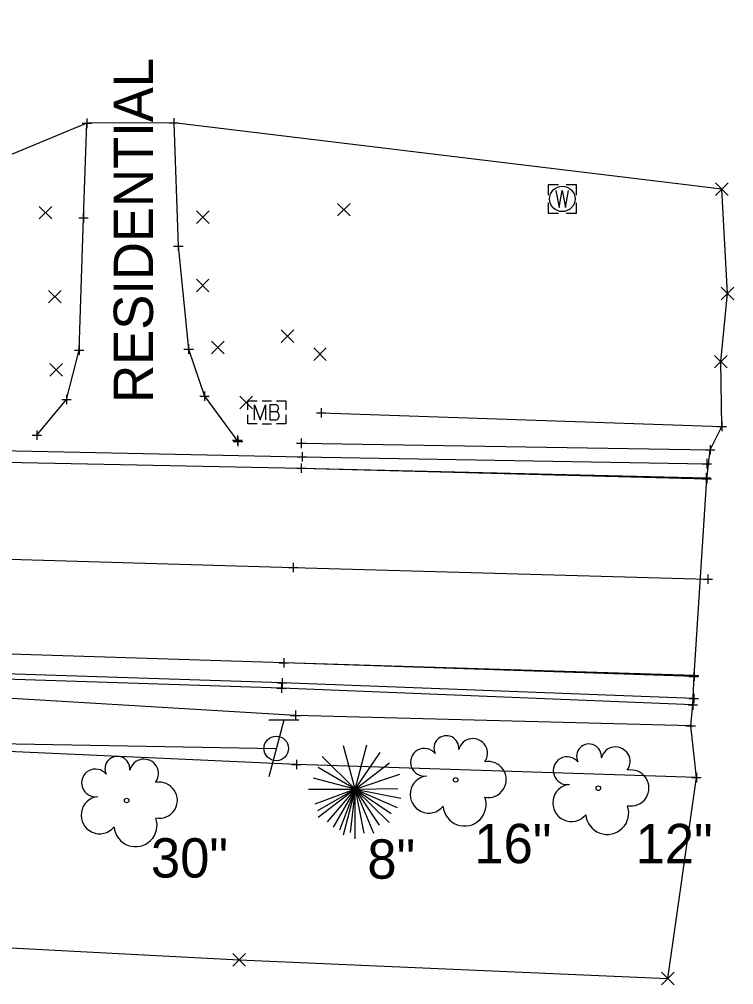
# Model space of a CAD drawing. Extents: x 2005176 to 2005823, y 572472 to 572942.
# Drawn here: x 2005747.1 to 2005822.9, y 572556.3 to 572658.6 of the extents above; entities that cross this region are included whole.
import ezdxf

# ---------------------------------------------------------------- set-up
doc = ezdxf.new("R2010")
doc.units = 0
for name, color, linetype in [('DR_X_Text', 7, 'Continuous'), ('GE_X_Alignment_1000_Stations', 7, 'Continuous'), ('GE_X_Alignment_100_Bearings', 7, 'Continuous'), ('GE_X_Alignment_100_Cardinal_Points', 7, 'Continuous'), ('GE_X_Alignment_100_Curve_Data', 7, 'Continuous'), ('GE_X_Alignment_100_Distances', 7, 'Continuous'), ('GE_X_Alignment_100_Stations', 7, 'Continuous'), ('GE_X_Alignment_500_Cardinal_Points', 7, 'Continuous'), ('GE_X_Alignment_500_Distances', 7, 'Continuous'), ('PV_X_COP', 7, 'Continuous'), ('SC_Scratch1', 7, 'Continuous'), ('SC_Scratch10', 7, 'Continuous'), ('SC_Scratch8', 7, 'Continuous'), ('SV_P_Mon_Cells_Set', 7, 'Continuous'), ('SV_X_Random_Point', 7, 'Continuous'), ('SV_X_Shot_Marker', 7, 'Continuous'), ('SV_X_Terrain_Boundary', 7, 'Continuous'), ('UT_X_Overhead_Telecom', 7, 'Continuous'), ('VG_X_Text', 7, 'Continuous')]:
    doc.layers.add(name, color=color, linetype=linetype)

msp = doc.modelspace()

# ---------------------------------------------------------------- linework, layer by layer
at = {"layer": 'GE_X_Alignment_1000_Stations'}
msp.add_line((2005804.71, 572639.55), (2005804.71, 572639.55), dxfattribs=at)
for points in [[(2005804.31, 572641.05), (2005803.21, 572641.05), (2005803.21, 572639.95)], [(2005806.21, 572639.95), (2005806.21, 572641.05), (2005805.11, 572641.05)], [(2005804.04, 572640.45), (2005804.38, 572638.65), (2005804.71, 572640.45), (2005805.04, 572638.65), (2005805.38, 572640.45)], [(2005803.21, 572639.15), (2005803.21, 572638.05), (2005804.31, 572638.05)], [(2005805.11, 572638.05), (2005806.21, 572638.05), (2005806.21, 572639.15)]]:
    msp.add_lwpolyline(points, dxfattribs=at)
msp.add_circle((2005804.71, 572639.55), 1.35, dxfattribs=at)
at = {"layer": 'GE_X_Alignment_100_Bearings'}
for points in [[(2005220.7, 572626.42), (2005272.19, 572624.71), (2005322.24, 572623.5), (2005370.59, 572622.7), (2005425.14, 572621.65), (2005477.36, 572620.84), (2005525.07, 572619.6), (2005576.7, 572617.86), (2005628.14, 572615.99), (2005678.39, 572614.09), (2005728.23, 572612.03), (2005777.04, 572611.02), (2005819.95, 572609.99)], [(2005818.64, 572588.97), (2005775.2, 572590.4), (2005728.29, 572591.88), (2005676.68, 572593.61), (2005626.55, 572595.19), (2005577.83, 572596.72), (2005526.97, 572598.44), (2005477.01, 572599.53), (2005423.67, 572600.7), (2005368.75, 572601.99), (2005321.74, 572602.99), (2005266.72, 572604.35), (2005220.03, 572605.66)]]:
    msp.add_lwpolyline(points, dxfattribs=at)
at = {"layer": 'GE_X_Alignment_100_Cardinal_Points'}
msp.add_lwpolyline([(2005220.5, 572615.99), (2005272.51, 572614.37), (2005322.2, 572613.2), (2005370.62, 572612.29), (2005424.94, 572611.27), (2005476.5, 572610.17), (2005524.32, 572608.79), (2005576.49, 572607.4), (2005627.69, 572605.77), (2005677.11, 572603.68), (2005728.03, 572601.92), (2005776.18, 572600.5), (2005820.14, 572599.28)], dxfattribs=at)
at = {"layer": 'GE_X_Alignment_100_Curve_Data'}
for points in [[(2005749.01, 572614.52), (2005752.14, 572618.29), (2005753.5, 572623.53), (2005753.95, 572637.53), (2005754.32, 572647.56)], [(2005763.54, 572647.6), (2005764, 572634.55), (2005765.1, 572623.65), (2005766.79, 572618.66), (2005770.33, 572613.87)]]:
    msp.add_lwpolyline(points, dxfattribs=at)
at = {"layer": 'GE_X_Alignment_100_Distances'}
for points in [[(2005220.68, 572626.38), (2005272.19, 572624.71), (2005322.24, 572623.5), (2005370.59, 572622.7), (2005425.14, 572621.65), (2005477.36, 572620.84), (2005525.07, 572619.6), (2005576.7, 572617.86), (2005628.14, 572615.99), (2005678.39, 572614.09), (2005728.23, 572612.03), (2005777.04, 572611.02), (2005820.02, 572609.9)], [(2005818.7, 572589.05), (2005775.2, 572590.4), (2005728.29, 572591.88), (2005676.68, 572593.61), (2005626.55, 572595.19), (2005577.83, 572596.72), (2005526.97, 572598.44), (2005477.01, 572599.53), (2005423.67, 572600.7), (2005368.75, 572601.99), (2005321.74, 572602.99), (2005266.72, 572604.35), (2005220.06, 572605.65)]]:
    msp.add_lwpolyline(points, dxfattribs=at)
at = {"layer": 'GE_X_Alignment_100_Stations'}
for points in [[(2005779.15, 572616.9), (2005821.63, 572615.44)], [(2005818.32, 572583.75), (2005776.41, 572584.84), (2005733.38, 572587.41), (2005688.89, 572587.43), (2005643.67, 572588.24), (2005617.3, 572589.8), (2005601, 572590.26), (2005586.78, 572589.84), (2005574.29, 572588.4), (2005565.07, 572583.34)]]:
    msp.add_lwpolyline(points, dxfattribs=at)
at = {"layer": 'GE_X_Alignment_500_Cardinal_Points'}
msp.add_lwpolyline([(2005818.94, 572578.27), (2005776.52, 572579.63), (2005733.4, 572581.57), (2005688.76, 572580.93), (2005659.16, 572582.97), (2005643.63, 572584.23), (2005617.78, 572585.7), (2005598.98, 572587.73), (2005575.61, 572583.45)], dxfattribs=at)
at = {"layer": 'GE_X_Alignment_500_Distances'}
msp.add_lwpolyline([(2005220.4, 572616.04), (2005272.51, 572614.37), (2005322.2, 572613.2), (2005370.62, 572612.29), (2005424.94, 572611.27), (2005476.5, 572610.17), (2005524.32, 572608.79), (2005576.49, 572607.4), (2005627.69, 572605.77), (2005677.11, 572603.68), (2005728.03, 572601.92), (2005776.18, 572600.5), (2005820.14, 572599.26)], dxfattribs=at)
at = {"layer": 'PV_X_COP'}
for p, q in [((2005772.88, 572618.16), (2005773.88, 572618.16)), ((2005773.39, 572616.94), (2005773.39, 572616.94)), ((2005772.88, 572615.72), (2005773.88, 572615.72))]:
    msp.add_line(p, q, dxfattribs=at)
for points in [[(2005771.39, 572617.19), (2005771.39, 572618.16), (2005772.36, 572618.16)], [(2005772.09, 572616.14), (2005772.09, 572617.74), (2005772.67, 572616.14), (2005773.23, 572617.74), (2005773.23, 572616.14)], [(2005774.41, 572617.01), (2005774.48, 572617.07), (2005774.51, 572617.11), (2005774.54, 572617.15), (2005774.55, 572617.17), (2005774.58, 572617.23), (2005774.59, 572617.26), (2005774.61, 572617.35), (2005774.61, 572617.39), (2005774.61, 572617.44), (2005774.6, 572617.51), (2005774.58, 572617.58), (2005774.54, 572617.63), (2005774.48, 572617.68), (2005774.43, 572617.7), (2005774.4, 572617.72), (2005774.34, 572617.74), (2005773.72, 572617.74), (2005773.72, 572616.14), (2005774.41, 572616.14), (2005774.5, 572616.19), (2005774.58, 572616.26), (2005774.64, 572616.36), (2005774.68, 572616.47), (2005774.69, 572616.58), (2005774.69, 572616.66), (2005774.66, 572616.73), (2005774.61, 572616.85), (2005774.55, 572616.92), (2005774.41, 572617.01), (2005773.72, 572617.01)], [(2005774.4, 572618.16), (2005775.39, 572618.16), (2005775.39, 572617.19)], [(2005772.36, 572615.72), (2005771.39, 572615.72), (2005771.39, 572616.69)], [(2005775.39, 572616.69), (2005775.39, 572615.72), (2005774.4, 572615.72)]]:
    msp.add_lwpolyline(points, dxfattribs=at)
at = {"layer": 'SC_Scratch1'}
for p, q in [((2005776.79, 572584.34), (2005773.59, 572584.34)), ((2005775.19, 572584.34), (2005773.59, 572578.34))]:
    msp.add_line(p, q, dxfattribs=at)
msp.add_circle((2005774.39, 572581.34), 1.3, dxfattribs=at)
at = {"layer": 'SC_Scratch10'}
for points in [[(2005777.04, 572613.66), (2005820.38, 572612.97)], [(2005818.55, 572585.94), (2005774.93, 572587.72), (2005728.19, 572589.23), (2005676.71, 572591.12), (2005626.89, 572592.62), (2005577.77, 572593.78), (2005527.62, 572595.75), (2005477.17, 572596.25), (2005467.62, 572596.6)]]:
    msp.add_lwpolyline(points, dxfattribs=at)
at = {"layer": 'SC_Scratch8'}
for points in [[(2005220.9, 572628.72), (2005272.16, 572627.13), (2005321.83, 572625.74), (2005370.81, 572625), (2005424.98, 572624.56), (2005477.31, 572623.7), (2005525.21, 572621.63), (2005576.56, 572620.01), (2005628.24, 572617.89), (2005678.25, 572615.23), (2005728.27, 572613.25), (2005777.12, 572612.24), (2005820.02, 572611.5)], [(2005818.66, 572586.64), (2005775.01, 572588.28), (2005728.16, 572589.79), (2005676.75, 572591.58), (2005626.73, 572593.57), (2005577.92, 572595.76), (2005527.42, 572597.32), (2005476.91, 572598.65), (2005423.43, 572599.27), (2005368.77, 572600.6), (2005321.59, 572601.67), (2005267.03, 572602.73), (2005220.03, 572603.93)]]:
    msp.add_lwpolyline(points, dxfattribs=at)
at = {"layer": 'SV_P_Mon_Cells_Set'}
for p, q in [((2005753.82, 572647.56), (2005754.82, 572647.56)), ((2005754.32, 572648.06), (2005754.32, 572647.06)), ((2005754.32, 572647.56), (2005754.32, 572647.56)), ((2005763.04, 572647.6), (2005764.04, 572647.6)), ((2005763.54, 572648.1), (2005763.54, 572647.1)), ((2005763.54, 572647.6), (2005763.54, 572647.6)), ((2005753.95, 572638.03), (2005753.95, 572637.03)), ((2005753.45, 572637.53), (2005754.45, 572637.53)), ((2005753.95, 572637.53), (2005753.95, 572637.53)), ((2005764, 572635.05), (2005764, 572634.05)), ((2005763.5, 572634.55), (2005764.5, 572634.55)), ((2005764, 572634.55), (2005764, 572634.55)), ((2005753.5, 572624.03), (2005753.5, 572623.03)), ((2005764.6, 572623.65), (2005765.6, 572623.65)), ((2005765.1, 572624.15), (2005765.1, 572623.15)), ((2005765.1, 572623.65), (2005765.1, 572623.65)), ((2005753, 572623.53), (2005754, 572623.53)), ((2005753.5, 572623.53), (2005753.5, 572623.53)), ((2005752.14, 572618.79), (2005752.14, 572617.79)), ((2005766.29, 572618.66), (2005767.29, 572618.66)), ((2005766.79, 572619.16), (2005766.79, 572618.16)), ((2005766.79, 572618.66), (2005766.79, 572618.66)), ((2005751.64, 572618.29), (2005752.64, 572618.29)), ((2005752.14, 572618.29), (2005752.14, 572618.29)), ((2005778.65, 572616.9), (2005779.65, 572616.9)), ((2005779.15, 572617.4), (2005779.15, 572616.4)), ((2005779.15, 572616.9), (2005779.15, 572616.9)), ((2005821.63, 572615.94), (2005821.63, 572614.94)), ((2005748.51, 572614.52), (2005749.51, 572614.52)), ((2005749.01, 572615.02), (2005749.01, 572614.02)), ((2005749.01, 572614.52), (2005749.01, 572614.52)), ((2005770.26, 572614.5), (2005770.26, 572613.5)), ((2005821.13, 572615.44), (2005822.13, 572615.44)), ((2005821.63, 572615.44), (2005821.63, 572615.44)), ((2005769.76, 572614), (2005770.76, 572614)), ((2005769.83, 572613.87), (2005770.83, 572613.87)), ((2005770.26, 572614), (2005770.26, 572614)), ((2005770.33, 572614.37), (2005770.33, 572613.37)), ((2005770.33, 572613.87), (2005770.33, 572613.87)), ((2005776.54, 572613.66), (2005777.54, 572613.66)), ((2005777.04, 572614.16), (2005777.04, 572613.16)), ((2005777.04, 572613.66), (2005777.04, 572613.66)), ((2005820.38, 572613.47), (2005820.38, 572612.47)), ((2005777.12, 572612.74), (2005777.12, 572611.74)), ((2005819.88, 572612.97), (2005820.88, 572612.97)), ((2005820.38, 572612.97), (2005820.38, 572612.97)), ((2005776.62, 572612.24), (2005777.62, 572612.24)), ((2005777.04, 572611.52), (2005777.04, 572610.52)), ((2005777.04, 572611.52), (2005777.04, 572610.52)), ((2005777.12, 572612.24), (2005777.12, 572612.24)), ((2005819.52, 572611.5), (2005820.52, 572611.5)), ((2005820.02, 572612), (2005820.02, 572611)), ((2005820.02, 572611.5), (2005820.02, 572611.5)), ((2005776.54, 572611.02), (2005777.54, 572611.02)), ((2005776.54, 572611.02), (2005777.54, 572611.02)), ((2005777.04, 572611.02), (2005777.04, 572611.02)), ((2005777.04, 572611.02), (2005777.04, 572611.02)), ((2005819.95, 572610.49), (2005819.95, 572609.49)), ((2005820.02, 572610.4), (2005820.02, 572609.4)), ((2005819.45, 572609.99), (2005820.45, 572609.99)), ((2005819.52, 572609.9), (2005820.52, 572609.9)), ((2005819.95, 572609.99), (2005819.95, 572609.99)), ((2005820.02, 572609.9), (2005820.02, 572609.9)), ((2005775.68, 572600.5), (2005776.68, 572600.5)), ((2005775.68, 572600.5), (2005776.68, 572600.5)), ((2005776.18, 572601), (2005776.18, 572600)), ((2005776.18, 572601), (2005776.18, 572600)), ((2005776.18, 572600.5), (2005776.18, 572600.5)), ((2005776.18, 572600.5), (2005776.18, 572600.5)), ((2005819.64, 572599.28), (2005820.64, 572599.28)), ((2005819.64, 572599.26), (2005820.64, 572599.26)), ((2005820.14, 572599.78), (2005820.14, 572598.78)), ((2005820.14, 572599.76), (2005820.14, 572598.76)), ((2005820.14, 572599.28), (2005820.14, 572599.28)), ((2005820.14, 572599.26), (2005820.14, 572599.26)), ((2005774.7, 572590.4), (2005775.7, 572590.4)), ((2005774.7, 572590.4), (2005775.7, 572590.4)), ((2005775.2, 572590.9), (2005775.2, 572589.9)), ((2005775.2, 572590.9), (2005775.2, 572589.9)), ((2005775.2, 572590.4), (2005775.2, 572590.4)), ((2005775.2, 572590.4), (2005775.2, 572590.4)), ((2005818.14, 572588.97), (2005819.14, 572588.97)), ((2005818.2, 572589.05), (2005819.2, 572589.05)), ((2005818.64, 572589.47), (2005818.64, 572588.47)), ((2005818.64, 572588.97), (2005818.64, 572588.97)), ((2005818.7, 572589.55), (2005818.7, 572588.55)), ((2005818.7, 572589.05), (2005818.7, 572589.05)), ((2005774.51, 572588.28), (2005775.51, 572588.28)), ((2005774.93, 572588.22), (2005774.93, 572587.22)), ((2005775.01, 572588.78), (2005775.01, 572587.78)), ((2005775.01, 572588.28), (2005775.01, 572588.28)), ((2005774.43, 572587.72), (2005775.43, 572587.72)), ((2005774.93, 572587.72), (2005774.93, 572587.72)), ((2005818.66, 572587.14), (2005818.66, 572586.14)), ((2005818.05, 572585.94), (2005819.05, 572585.94)), ((2005818.16, 572586.64), (2005819.16, 572586.64)), ((2005818.55, 572586.44), (2005818.55, 572585.44)), ((2005818.55, 572585.94), (2005818.55, 572585.94)), ((2005818.66, 572586.64), (2005818.66, 572586.64)), ((2005775.91, 572584.84), (2005776.91, 572584.84)), ((2005776.41, 572585.34), (2005776.41, 572584.34)), ((2005776.41, 572584.84), (2005776.41, 572584.84)), ((2005818.32, 572584.25), (2005818.32, 572583.25)), ((2005817.82, 572583.75), (2005818.82, 572583.75)), ((2005818.32, 572583.75), (2005818.32, 572583.75)), ((2005776.52, 572580.13), (2005776.52, 572579.13)), ((2005776.02, 572579.63), (2005777.02, 572579.63)), ((2005776.52, 572579.63), (2005776.52, 572579.63)), ((2005818.94, 572578.77), (2005818.94, 572577.77)), ((2005818.44, 572578.27), (2005819.44, 572578.27)), ((2005818.94, 572578.27), (2005818.94, 572578.27))]:
    msp.add_line(p, q, dxfattribs=at)
at = {"layer": 'SV_X_Random_Point'}
for p, q in [((2005820.95, 572639.92), (2005822.28, 572641.25)), ((2005820.95, 572641.25), (2005822.28, 572639.92)), ((2005780.89, 572637.74), (2005782.22, 572639.08)), ((2005780.89, 572639.08), (2005782.22, 572637.74)), ((2005749.26, 572637.43), (2005750.59, 572638.76)), ((2005749.26, 572638.76), (2005750.59, 572637.43)), ((2005765.93, 572636.94), (2005767.26, 572638.27)), ((2005765.93, 572638.27), (2005767.26, 572636.94)), ((2005765.92, 572629.7), (2005767.25, 572631.04)), ((2005765.92, 572631.04), (2005767.25, 572629.7)), ((2005750.25, 572628.53), (2005751.59, 572629.86)), ((2005750.25, 572629.86), (2005751.59, 572628.53)), ((2005821.55, 572628.87), (2005822.88, 572630.21)), ((2005821.55, 572630.21), (2005822.88, 572628.87)), ((2005774.9, 572624.34), (2005776.24, 572625.67)), ((2005774.9, 572625.67), (2005776.24, 572624.34)), ((2005767.52, 572623.14), (2005768.86, 572624.48)), ((2005767.52, 572624.48), (2005768.86, 572623.14)), ((2005778.36, 572622.45), (2005779.69, 572623.79)), ((2005778.36, 572623.79), (2005779.69, 572622.45)), ((2005820.85, 572621.65), (2005822.19, 572622.98)), ((2005820.85, 572622.98), (2005822.19, 572621.65)), ((2005750.39, 572620.79), (2005751.73, 572622.12)), ((2005750.39, 572622.12), (2005751.73, 572620.79)), ((2005770.54, 572617.31), (2005771.88, 572618.65)), ((2005770.54, 572618.65), (2005771.88, 572617.31)), ((2005769.78, 572558.29), (2005771.11, 572559.63)), ((2005769.78, 572559.63), (2005771.11, 572558.29)), ((2005815.24, 572556.31), (2005816.57, 572557.65)), ((2005815.24, 572557.65), (2005816.57, 572556.31))]:
    msp.add_line(p, q, dxfattribs=at)
at = {"layer": 'SV_X_Shot_Marker'}
for p, q in [((2005782.75, 572577.01), (2005784, 572581.71)), ((2005782.75, 572577.01), (2005781.51, 572581.63)), ((2005782.75, 572577.01), (2005785.4, 572580.9)), ((2005782.75, 572577.01), (2005779.26, 572580.5)), ((2005782.75, 572577.01), (2005786.4, 572579.82)), ((2005782.75, 572577.01), (2005778.84, 572579.31)), ((2005782.75, 572577.01), (2005778.33, 572578.2)), ((2005782.75, 572577.01), (2005787.48, 572578.62)), ((2005777.81, 572577.01), (2005782.75, 572577.01)), ((2005782.75, 572577.01), (2005778.46, 572575.45)), ((2005782.75, 572577.01), (2005778.76, 572574.73)), ((2005782.75, 572577.01), (2005778.84, 572574.02)), ((2005782.75, 572577.01), (2005779.8, 572573.55)), ((2005782.75, 572577.01), (2005780.43, 572573)), ((2005782.75, 572577.01), (2005781.08, 572572.67)), ((2005782.75, 572577.01), (2005781.48, 572572.16)), ((2005782.75, 572577.01), (2005782.21, 572572.42)), ((2005782.75, 572577.01), (2005787.26, 572577.11)), ((2005782.75, 572571.77), (2005782.75, 572577.01)), ((2005782.75, 572577.01), (2005783.67, 572572.38)), ((2005782.75, 572577.01), (2005784.68, 572572.35)), ((2005782.75, 572577.01), (2005785.28, 572573.22)), ((2005782.75, 572577.01), (2005786.34, 572573.49)), ((2005782.75, 572577.01), (2005786.57, 572574.46)), ((2005782.75, 572577.01), (2005787.21, 572575.07)), ((2005782.75, 572577.01), (2005787.58, 572576.06))]:
    msp.add_line(p, q, dxfattribs=at)
for centre in [(2005793.4, 572578.01), (2005808.53, 572577.12), (2005758.53, 572575.82)]:
    msp.add_circle(centre, 0.24, dxfattribs=at)
for centre, radius, start, end in [((2005792.42, 572581.37), 1.32, 354.0047, 205.9741), ((2005795.23, 572580.83), 1.55, 323.83, 165.0376), ((2005807.54, 572580.49), 1.32, 354.0047, 205.9741), ((2005790.09, 572579.87), 1.47, 39.0625, 279.5412), ((2005810.35, 572579.95), 1.55, 323.83, 165.0376), ((2005757.54, 572579.18), 1.32, 354.0047, 205.9741), ((2005760.35, 572578.65), 1.55, 323.83, 165.0376), ((2005796.86, 572578.04), 1.91, 259.1453, 101.4596), ((2005805.22, 572578.98), 1.47, 39.0625, 279.5412), ((2005755.22, 572577.68), 1.47, 39.0625, 279.5412), ((2005811.99, 572577.15), 1.91, 259.1453, 101.4596), ((2005761.99, 572575.85), 1.91, 259.1453, 101.4596), ((2005790.55, 572576.46), 1.97, 96.1722, 320.5737), ((2005805.67, 572575.57), 1.97, 96.1722, 320.5737), ((2005755.67, 572574.27), 1.97, 96.1722, 320.5737), ((2005794.35, 572575.4), 2.28, 184.9476, 19.4572), ((2005809.47, 572574.51), 2.28, 184.9476, 19.4572), ((2005759.47, 572573.21), 2.28, 184.9476, 19.4572)]:
    msp.add_arc(centre, radius, start, end, dxfattribs=at)
at = {"layer": 'SV_X_Terrain_Boundary'}
msp.add_lwpolyline([(2005632.87, 572562.76), (2005676.67, 572561.82), (2005723.3, 572561.43), (2005770.44, 572558.96), (2005815.9, 572556.98), (2005818.94, 572578.27), (2005818.32, 572583.75), (2005818.55, 572585.94), (2005818.7, 572589.05), (2005820.02, 572609.9), (2005820.38, 572612.97), (2005821.63, 572615.44), (2005821.52, 572622.31), (2005822.21, 572629.54), (2005821.61, 572640.59), (2005763.54, 572647.6), (2005754.32, 572647.56), (2005734.01, 572639.17), (2005682.42, 572646.03), (2005631.48, 572658.58)], dxfattribs=at)
at = {"layer": 'UT_X_Overhead_Telecom'}
msp.add_line((2005612.94, 572584.19), (2005774.39, 572581.34), dxfattribs=at)

# ---------------------------------------------------------------- texts
at = {"layer": 'DR_X_Text'}
msp.add_text('RESIDENTIAL', height=4.1667, rotation=90, dxfattribs=at).set_placement((2005761.32, 572617.95))
at = {"layer": 'VG_X_Text'}
for s, p in [('16"', (2005795.39, 572569.18)), ('12"', (2005812.48, 572569.18)), ('30"', (2005761.1, 572567.66)), ('8"', (2005784.04, 572567.54))]:
    msp.add_text(s, height=4.167, dxfattribs=at).set_placement(p)

doc.saveas('drawing.dxf')
